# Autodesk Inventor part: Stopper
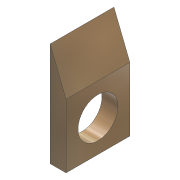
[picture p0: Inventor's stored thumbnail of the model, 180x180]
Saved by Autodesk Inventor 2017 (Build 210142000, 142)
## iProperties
Part Number: Stopper
Material: 木材(カエデ)
Document SubType Name: Modeling
Designer: kyushu-hep
Density: 0.67 g/cm^3
Appearance: ナチュラル カエデ材 - 光沢 濃い着色
Author: kyushu-hep
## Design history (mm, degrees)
sketch "スケッチ1"
  geometry: L1 (0, 9.98)-(-2, 4.98); L2 (-2, 4.98)-(-2, -3.02); L3 (-2, -3.02)-(0, -3.02); L4 (0, -3.02)-(0, 9.98); 1 further point
  constraints: 8 end point, 2 perpendicular, 1 vertical
  dimensions: "d0" = 8 distance of L1.end L2.end; "d1" = 2 distance between parallel lines of L4 L2; "d2" = 5 vertical distance of L1.end L1.start
extrude "押し出し1" new body sketch "スケッチ1" distance "d3" = 8; taper "d4" = 0 deg
sketch "スケッチ2"
  geometry: L1 (8, 0)-(8, 8) reference; L2 (8, 0)-(-5, 0) reference; C1 r 2.5 at (4, 4); 1 further point
  constraints: 1 centre point
  dimensions: "d5" = 5 diameter of C1; "d6" = 4 distance from line of L1 C1.centre; "d7" = 4 distance from line of L2 C1.centre
extrude "押し出し2" cut sketch "スケッチ2" distance "d8" = 2; taper "d9" = 0 deg
node "ソリッド1"
